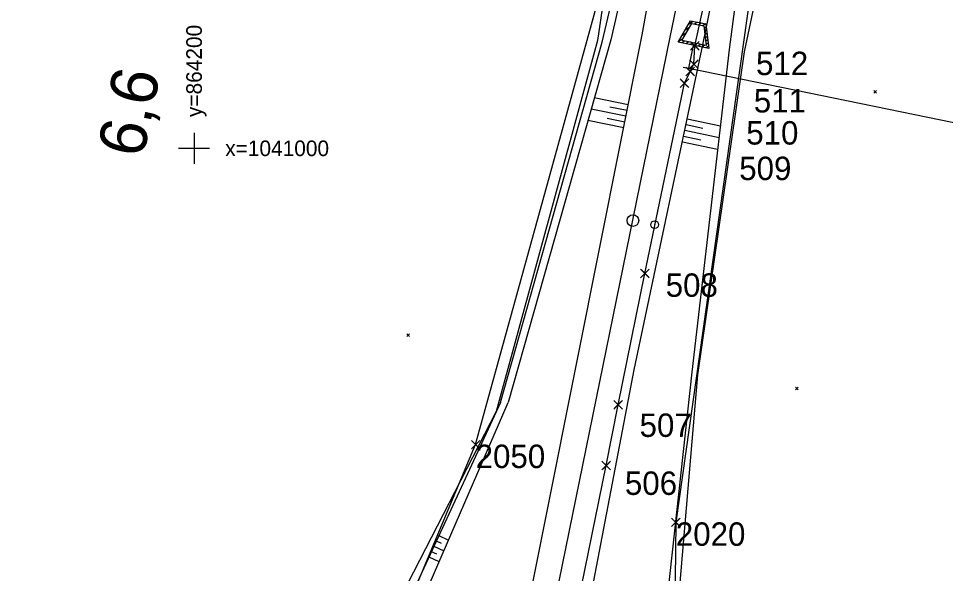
# Model space of a CAD drawing. Extents: x -866402 to -860377, y -1041908 to -1038598.
# Drawn here: x -864222.5 to -864103.6, y -1041054.5 to -1040983.4 of the extents above; entities that cross this region are included whole.
import ezdxf

# ---------------------------------------------------------------- set-up
doc = ezdxf.new("R2010")
doc.units = 0
for name, color, linetype in [('PS 02 trasa', 7, 'Continuous'), ('SZDC', 7, 'Continuous'), ('Vrstva 1', 7, 'Continuous'), ('Vrstva 17', 7, 'Continuous'), ('Vrstva 48', 7, 'Continuous'), ('Vrstva 49', 7, 'Continuous'), ('Vrstva 5', 7, 'Continuous'), ('Vrstva 60', 7, 'Continuous'), ('Vrstva 7', 7, 'Continuous')]:
    doc.layers.add(name, color=color, linetype=linetype)

msp = doc.modelspace()

# ---------------------------------------------------------------- linework, layer by layer
at = {"layer": 'PS 02 trasa'}
msp.add_lwpolyline([(-864152.15, -1041065.15), (-864147.14, -1041040.65), (-864145.62, -1041032.86), (-864142.19, -1041016.03), (-864137.11, -1040991.66), (-864136.37, -1040990.15), (-864135.9, -1040989.22), (-864135.78, -1040986.86), (-864134, -1040978.71), (-864132.58, -1040973.01), (-864131.14, -1040967.38), (-864130.28, -1040960.93), (-864130.35, -1040958.56), (-864129.42, -1040953.97), (-864129.15, -1040952.07)], dxfattribs=at)
at = {"layer": 'SZDC'}
for points in [[(-864124.2, -1040948.66), (-864125.63, -1040958.77), (-864138.22, -1041047.93), (-864138.66, -1041084.26), (-864136.94, -1041093.86), (-864135.28, -1041103.15), (-864140.05, -1041118.73), (-864153.01, -1041128.83), (-864154.64, -1041130.09), (-864167.69, -1041178.99), (-864170.43, -1041189.44), (-864176.98, -1041214.36), (-864151.36, -1041242.08), (-864141.98, -1041248.23), (-864158.12, -1041267.29), (-864199.89, -1041314.35)], [(-864222.51, -1041305.5), (-864212.56, -1041285.23), (-864207.2, -1041260.82), (-864199.56, -1041226.02), (-864193.94, -1041189.69), (-864192.64, -1041181.32), (-864192.47, -1041180.21), (-864181.03, -1041111.42), (-864180.31, -1041090.77), (-864179.79, -1041075.79), (-864171.7, -1041056.54), (-864163.89, -1041037.97), (-864142.49, -1040960.45), (-864141.92, -1040958.4), (-864151.94, -1040958.11)]]:
    msp.add_lwpolyline(points, dxfattribs=at)
at = {"layer": 'Vrstva 1'}
msp.add_lwpolyline([(-864190.9, -1041239.89), (-864187.65, -1041224.26), (-864179.08, -1041182.25), (-864176.19, -1041168.17), (-864167.63, -1041126.21), (-864158.95, -1041083.67), (-864157.99, -1041079.01), (-864156.21, -1041070.31), (-864147.52, -1041027.82), (-864138.93, -1040985.78), (-864136.16, -1040972.3), (-864133.07, -1040957.15), (-864132.45, -1040954.14), (-864131.09, -1040947.46), (-864122.54, -1040905.52), (-864114.14, -1040864.42), (-864106.24, -1040825.76)], dxfattribs=at)
at = {"layer": 'Vrstva 17'}
for p, q in [((-864146.24, -1040972.55), (-864148.26, -1040986.17)), ((-864148.26, -1040986.17), (-864161.25, -1041033.74)), ((-864161.25, -1041033.74), (-864176.8, -1041063.92))]:
    msp.add_line(p, q, dxfattribs=at)
msp.add_lwpolyline([(-864139.16, -1041073.23), (-864135.4, -1041029.01), (-864129.43, -1040987.63), (-864126.42, -1040973.47), (-864107.21, -1040959.57)], dxfattribs=at)
at = {"layer": 'Vrstva 48'}
for p, q in [((-864144.31, -1040994.43), (-864148.68, -1040993.55)), ((-864144.46, -1040995.16), (-864146.67, -1040994.72)), ((-864144.61, -1040995.9), (-864149.09, -1040995)), ((-864144.9, -1040997.37), (-864149.5, -1040996.45)), ((-864144.75, -1040996.63), (-864147.03, -1040996.18)), ((-864136.91, -1040996.96), (-864134.75, -1040997.42)), ((-864136.76, -1040996.22), (-864132.51, -1040997.13)), ((-864137.22, -1040998.43), (-864135, -1040998.9)), ((-864137.07, -1040997.69), (-864132.68, -1040998.62)), ((-864137.38, -1040999.16), (-864132.86, -1041000.12)), ((-864168.95, -1041050.31), (-864168.32, -1041050.6)), ((-864168.63, -1041049.63), (-864167.39, -1041050.21)), ((-864169.58, -1041051.67), (-864168.93, -1041051.97)), ((-864169.26, -1041050.99), (-864167.99, -1041051.58)), ((-864169.89, -1041052.35), (-864168.59, -1041052.96))]:
    msp.add_line(p, q, dxfattribs=at)
at = {"layer": 'Vrstva 49'}
for p, q in [((-864131.38, -1040987.35), (-864136.16, -1041028.67)), ((-864112.83, -1040992.59), (-864112.47, -1040992.94)), ((-864112.83, -1040992.94), (-864112.47, -1040992.59)), ((-864172.72, -1041023.77), (-864172.37, -1041024.12)), ((-864172.72, -1041024.12), (-864172.37, -1041023.77)), ((-864136.16, -1041028.67), (-864141.01, -1041073.22)), ((-864122.87, -1041030.59), (-864122.52, -1041030.95)), ((-864122.87, -1041030.95), (-864122.52, -1041030.59)), ((-864160.72, -1041032.57), (-864175.24, -1041063.9)), ((-864173.52, -1041064.31), (-864159.73, -1041032.59))]:
    msp.add_line(p, q, dxfattribs=at)
for points in [[(-864150.8, -1041026.82), (-864142.52, -1040985.46), (-864140.16, -1040972.18), (-864138.93, -1040961.25)], [(-864160.72, -1041032.57), (-864147.67, -1040986.4), (-864144.39, -1040972.44), (-864141.6, -1040963.43)], [(-864141.6, -1040963.43), (-864143.41, -1040972.26), (-864146.57, -1040986.08), (-864159.73, -1041032.59)], [(-864134.7, -1040986.51), (-864131.94, -1040972.94), (-864130.47, -1040964.86)], [(-864127.51, -1040967.15), (-864129.65, -1040974.25), (-864131.38, -1040987.35)], [(-864163.95, -1041126.96), (-864155.16, -1041084.53), (-864151.72, -1041071.04), (-864143.58, -1041028.39), (-864134.7, -1040986.51)], [(-864170.78, -1041125.68), (-864162.34, -1041083.55), (-864159.29, -1041069.4), (-864150.8, -1041026.82)]]:
    msp.add_lwpolyline(points, dxfattribs=at)
at = {"layer": 'Vrstva 5'}
for p, q in [((-864200, -1040998), (-864200, -1041002)), ((-864202, -1041000), (-864198, -1041000))]:
    msp.add_line(p, q, dxfattribs=at)
at = {"layer": 'Vrstva 60'}
for p, q in [((-864135.33, -1040987.31), (-864136.33, -1040986.31)), ((-864135.33, -1040986.41), (-864136.33, -1040987.41)), ((-864136.23, -1040987.31), (-864135.23, -1040986.31)), ((-864136.23, -1040986.41), (-864135.23, -1040987.41)), ((-864135.78, -1040986.86), (-864135.78, -1040986.86)), ((-864135.45, -1040989.67), (-864136.45, -1040988.67)), ((-864135.45, -1040988.77), (-864136.45, -1040989.77)), ((-864136.35, -1040989.67), (-864135.35, -1040988.67)), ((-864136.35, -1040988.77), (-864135.35, -1040989.77)), ((-864135.92, -1040990.6), (-864136.92, -1040989.6)), ((-864135.92, -1040989.7), (-864136.92, -1040990.7)), ((-864136.82, -1040990.6), (-864135.82, -1040989.6)), ((-864136.82, -1040989.7), (-864135.82, -1040990.7)), ((-864136.37, -1040990.15), (-864136.37, -1040990.15)), ((-864135.9, -1040989.22), (-864135.9, -1040989.22)), ((-864136.67, -1040992.11), (-864137.67, -1040991.11)), ((-864136.67, -1040991.21), (-864137.67, -1040992.21)), ((-864137.57, -1040992.11), (-864136.57, -1040991.11)), ((-864137.57, -1040991.21), (-864136.57, -1040992.21)), ((-864137.11, -1040991.66), (-864137.11, -1040991.66)), ((-864141.74, -1041016.48), (-864142.74, -1041015.48)), ((-864141.74, -1041015.58), (-864142.74, -1041016.58)), ((-864142.64, -1041016.48), (-864141.64, -1041015.48)), ((-864142.64, -1041015.58), (-864141.64, -1041016.58)), ((-864142.19, -1041016.03), (-864142.19, -1041016.03)), ((-864145.17, -1041033.31), (-864146.17, -1041032.31)), ((-864145.17, -1041032.41), (-864146.17, -1041033.41)), ((-864146.07, -1041033.31), (-864145.07, -1041032.31)), ((-864146.07, -1041032.41), (-864145.07, -1041033.41)), ((-864145.62, -1041032.86), (-864145.62, -1041032.86)), ((-864163.44, -1041038.42), (-864164.44, -1041037.42)), ((-864163.44, -1041037.52), (-864164.44, -1041038.52)), ((-864164.34, -1041038.42), (-864163.34, -1041037.42)), ((-864164.34, -1041037.52), (-864163.34, -1041038.52)), ((-864163.89, -1041037.97), (-864163.89, -1041037.97)), ((-864146.69, -1041041.1), (-864147.69, -1041040.1)), ((-864146.69, -1041040.2), (-864147.69, -1041041.2)), ((-864147.59, -1041041.1), (-864146.59, -1041040.1)), ((-864147.59, -1041040.2), (-864146.59, -1041041.2)), ((-864147.14, -1041040.65), (-864147.14, -1041040.65)), ((-864137.78, -1041048.38), (-864138.78, -1041047.38)), ((-864137.78, -1041047.47), (-864138.78, -1041048.47)), ((-864138.68, -1041048.38), (-864137.68, -1041047.38)), ((-864138.68, -1041047.47), (-864137.68, -1041048.47)), ((-864138.22, -1041047.93), (-864138.22, -1041047.93))]:
    msp.add_line(p, q, dxfattribs=at)
at = {"layer": 'Vrstva 7'}
for p, q in [((-864137.9, -1040986.41), (-864136.32, -1040983.67)), ((-864137.45, -1040986.19), (-864136.18, -1040984)), ((-864135.98, -1040983.74), (-864136.59, -1040984.14)), ((-864136.32, -1040983.67), (-864134.36, -1040984.07)), ((-864136.18, -1040984), (-864134.62, -1040984.32)), ((-864135.46, -1040983.84), (-864135.82, -1040984.08)), ((-864134.94, -1040983.95), (-864135.3, -1040984.18)), ((-864134.42, -1040984.05), (-864134.78, -1040984.29)), ((-864134.36, -1040984.07), (-864133.98, -1040987.21)), ((-864136.9, -1040985.24), (-864137.43, -1040985.59)), ((-864136.48, -1040984.51), (-864137.01, -1040984.86)), ((-864134.62, -1040984.32), (-864134.31, -1040986.83)), ((-864134.32, -1040984.43), (-864134.58, -1040984.61)), ((-864134.27, -1040984.85), (-864134.53, -1040985.02)), ((-864134.22, -1040985.26), (-864134.48, -1040985.44)), ((-864133.98, -1040987.21), (-864137.9, -1040986.41)), ((-864137.32, -1040985.97), (-864137.85, -1040986.32)), ((-864134.31, -1040986.83), (-864137.45, -1040986.19)), ((-864137.09, -1040986.26), (-864137.45, -1040986.5)), ((-864136.57, -1040986.37), (-864136.92, -1040986.6)), ((-864136.05, -1040986.48), (-864136.41, -1040986.71)), ((-864135.53, -1040986.58), (-864135.89, -1040986.82)), ((-864134.17, -1040985.68), (-864134.43, -1040985.86)), ((-864134.12, -1040986.1), (-864134.38, -1040986.27)), ((-864134.07, -1040986.51), (-864134.33, -1040986.69)), ((-864136.54, -1040989.74), (-864135.94, -1040986.81)), ((-864135.01, -1040986.69), (-864135.37, -1040986.92)), ((-864134.49, -1040986.8), (-864134.85, -1040987.03)), ((-864134.01, -1040986.93), (-864134.33, -1040987.14)), ((-864137.28, -1040989.59), (-864135.81, -1040989.9)), ((-864136.54, -1040989.74), (-864080.82, -1041001.13)), ((-864140.98, -1041009.79), (-864140.88, -1041009.79))]:
    msp.add_line(p, q, dxfattribs=at)
for centre, radius in [((-864143.72, -1041009.26), 0.75), ((-864140.93, -1041009.79), 0.5)]:
    msp.add_circle(centre, radius, dxfattribs=at)

# ---------------------------------------------------------------- texts
at = {"layer": 'Vrstva 5'}
msp.add_text('y=864200', height=2, rotation=90, dxfattribs=at).set_placement((-864199, -1040996))
msp.add_text('x=1041000', height=2, dxfattribs=at).set_placement((-864196, -1041001))
at = {"layer": 'Vrstva 60'}
for s, p in [('512', (-864127.94, -1040990.62)), ('511', (-864128.22, -1040995.41)), ('510', (-864129.19, -1040999.52)), ('509', (-864130.09, -1041004.07)), ('508', (-864139.52, -1041019.03)), ('507', (-864142.87, -1041036.98)), ('2050', (-864163.89, -1041040.97)), ('506', (-864144.75, -1041044.41)), ('2020', (-864138.22, -1041050.93))]:
    msp.add_text(s, height=3, dxfattribs=at).set_placement(p)
at = {"layer": 'Vrstva 7'}
msp.add_text('6,6', height=6, rotation=78.4486, dxfattribs=at).set_placement((-864206.55, -1041001.37))

doc.saveas('drawing.dxf')
